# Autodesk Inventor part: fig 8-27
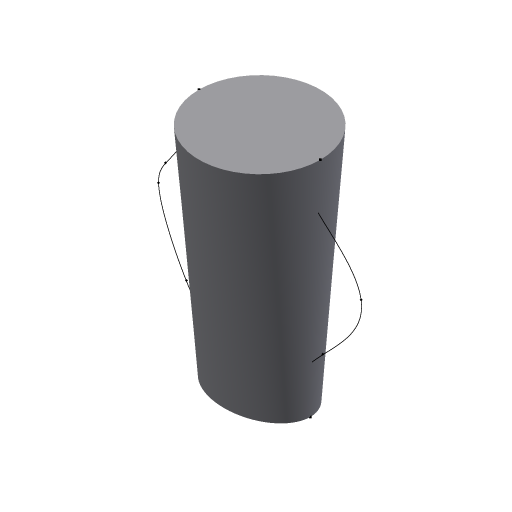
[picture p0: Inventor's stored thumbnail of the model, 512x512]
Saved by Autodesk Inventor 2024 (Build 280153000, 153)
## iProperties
Shininess: 64.0
Length Units: 11269
Angle Units: 11279
Time Units: 11290
Mass Units: 11283
Length Display Precision: 3
Angle Display Precision: 2
Compacted: True
Part Number: fig 8-27
Document SubType Name: Modeling
Created: 2002-12
Designer: deepak
Density: 1 g/cm^3
Material: Generic
Appearance: Default
Density: 0.0
Volumn: 0.0
Area: 0.0
PropertySet Name: Model Information
Control State: 0
Master: False
Checked Out: False
Author: deepak
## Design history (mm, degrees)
sketch "Sketch1"
  geometry: 2 further points; 1 other entity
  constraints: 1 coincident, 3 other
workplane "Work Plane1"
workplane "Work Plane2"
sketch "Sketch3"
  geometry: C1 r 60 at (0, 0); 1 further point
  constraints: 1 centre point, 1 coincident, 1 other
sketch "Sketch4"
  geometry: 8 further points
  constraints: 8 other
sketch "Sketch5"
  geometry: 6 further points
  constraints: 6 other
sketch "Sketch6"
  geometry: 6 further points
  constraints: 6 other
  dimensions: "d20" = 35 distance of point (0, 0) point (-35, 0); "d21" = 0 vertical distance of point (0, 0) point (-35, 0); "d22" = 225 vertical distance of point (0, 0) point (-60, 225); "d23" = 60 horizontal distance of point (0, 0) point (-60, 225); "d24" = 100 horizontal distance of point (0, 0) point (-100, 125); "d25" = 125 vertical distance of point (0, 0) point (-100, 125)
loft "Loft4" dims "d50" = 0, "d51" = 90 deg, "d52" = 0, "d53" = 90 deg
body "Solid1"
other parameters: "d5" = 125
